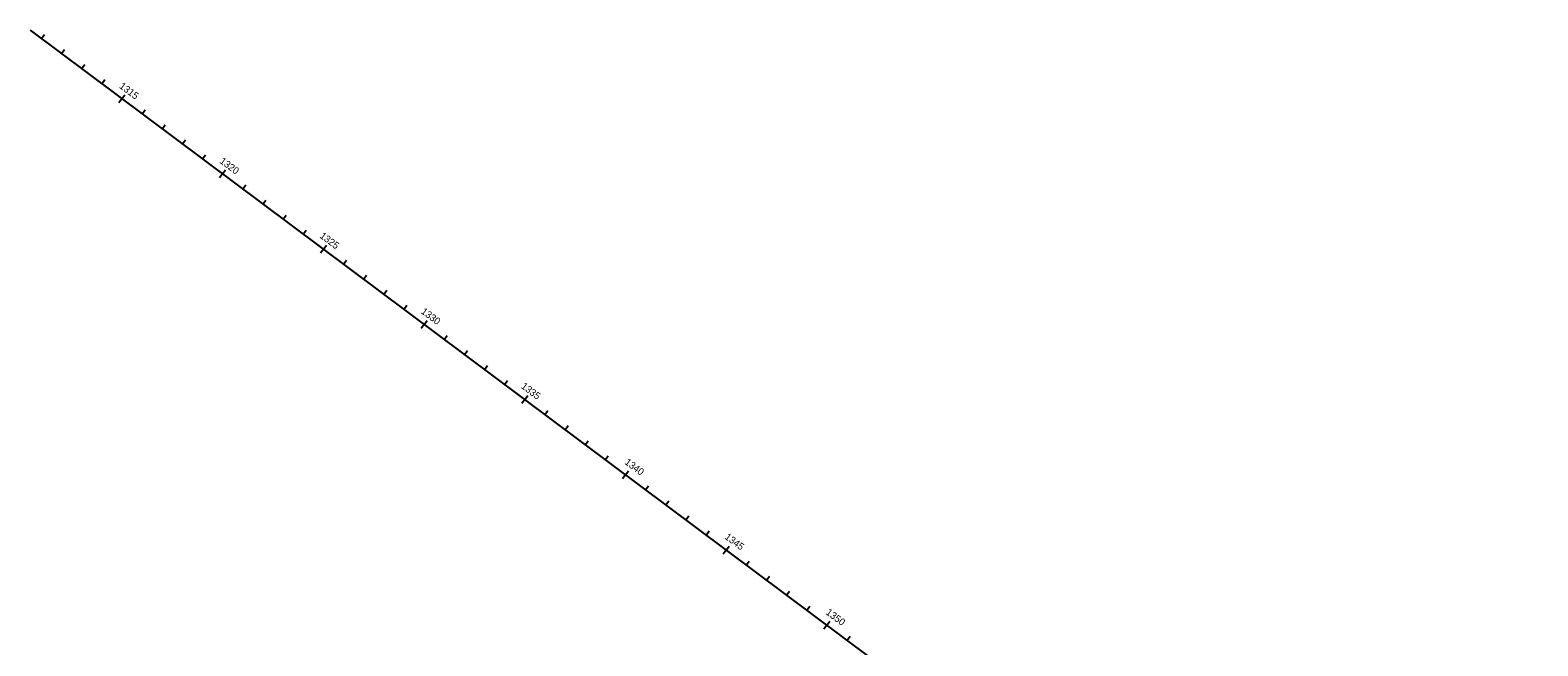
# Model space of a CAD drawing. Extents: x 2339300 to 2355400, y 360879 to 381052.
# Drawn here: x 2339300 to 2345299, y 372573 to 375020 of the extents above; entities that cross this region are included whole.
import ezdxf

# ---------------------------------------------------------------- set-up
doc = ezdxf.new("R2010")
doc.units = 0
for name, color, linetype in [('RD_HC_Cl', 7, 'Continuous'), ('RD_HC_Data_Tic', 7, 'Continuous'), ('RD_HC_TX_Sta50', 7, 'Continuous')]:
    doc.layers.add(name, color=color, linetype=linetype)

msp = doc.modelspace()

# ---------------------------------------------------------------- linework, layer by layer
at = {"layer": 'RD_HC_Cl'}
msp.add_line((2339299.7, 375020.3), (2345298.7, 370542.8), dxfattribs=at)
at = {"layer": 'RD_HC_Data_Tic'}
for p, q in [((2339344.4, 374987), (2339356.3, 375003)), ((2339424.5, 374927.2), (2339436.5, 374943.2)), ((2339504.6, 374867.4), (2339516.6, 374883.4)), ((2339584.8, 374807.5), (2339596.7, 374823.6)), ((2339664.9, 374747.7), (2339676.9, 374763.8)), ((2339664.9, 374747.7), (2339653, 374731.7)), ((2339745.1, 374687.9), (2339757, 374703.9)), ((2339825.2, 374628.1), (2339837.2, 374644.1)), ((2339905.3, 374568.3), (2339917.3, 374584.3)), ((2339985.5, 374508.5), (2339997.4, 374524.5)), ((2340065.6, 374448.7), (2340077.6, 374464.7)), ((2340065.6, 374448.7), (2340053.6, 374432.6)), ((2340145.8, 374388.9), (2340157.7, 374404.9)), ((2340225.9, 374329), (2340237.9, 374345.1)), ((2340306, 374269.2), (2340318, 374285.3)), ((2340386.2, 374209.4), (2340398.1, 374225.4)), ((2340466.3, 374149.6), (2340478.3, 374165.6)), ((2340466.3, 374149.6), (2340454.3, 374133.6)), ((2340546.5, 374089.8), (2340558.4, 374105.8)), ((2340626.6, 374030), (2340638.6, 374046)), ((2340706.7, 373970.2), (2340718.7, 373986.2)), ((2340786.9, 373910.3), (2340798.8, 373926.4)), ((2340867, 373850.5), (2340879, 373866.6)), ((2340867, 373850.5), (2340855, 373834.5)), ((2340947.1, 373790.7), (2340959.1, 373806.7)), ((2341027.3, 373730.9), (2341039.3, 373746.9)), ((2341107.4, 373671.1), (2341119.4, 373687.1)), ((2341187.6, 373611.3), (2341199.5, 373627.3)), ((2341267.7, 373551.5), (2341279.7, 373567.5)), ((2341267.7, 373551.5), (2341255.7, 373535.4)), ((2341347.8, 373491.7), (2341359.8, 373507.7)), ((2341428, 373431.8), (2341439.9, 373447.9)), ((2341508.1, 373372), (2341520.1, 373388.1)), ((2341588.3, 373312.2), (2341600.2, 373328.2)), ((2341668.4, 373252.4), (2341680.4, 373268.4)), ((2341668.4, 373252.4), (2341656.4, 373236.4)), ((2341748.5, 373192.6), (2341760.5, 373208.6)), ((2341828.7, 373132.8), (2341840.6, 373148.8)), ((2341908.8, 373073), (2341920.8, 373089)), ((2341989, 373013.1), (2342000.9, 373029.2)), ((2342069.1, 372953.3), (2342081.1, 372969.4)), ((2342069.1, 372953.3), (2342057.1, 372937.3)), ((2342149.2, 372893.5), (2342161.2, 372909.5)), ((2342229.4, 372833.7), (2342241.3, 372849.7)), ((2342309.5, 372773.9), (2342321.5, 372789.9)), ((2342389.7, 372714.1), (2342401.6, 372730.1)), ((2342469.8, 372654.3), (2342481.8, 372670.3)), ((2342469.8, 372654.3), (2342457.8, 372638.2)), ((2342549.9, 372594.5), (2342561.9, 372610.5))]:
    msp.add_line(p, q, dxfattribs=at)

# ---------------------------------------------------------------- texts
at = {"layer": 'RD_HC_TX_Sta50'}
for s, p in [('1315', (2339651.7, 374792.9)), ('1320', (2340051.1, 374494.7)), ('1325', (2340449.4, 374197.5)), ('1330', (2340852.3, 373896.8)), ('1335', (2341250.5, 373599.6)), ('1340', (2341662.6, 373297.8)), ('1345', (2342060.8, 373000.6)), ('1350', (2342462.9, 372700.4))]:
    msp.add_text(s, height=28, rotation=323.26372, dxfattribs=at).set_placement(p)

doc.saveas('drawing.dxf')
